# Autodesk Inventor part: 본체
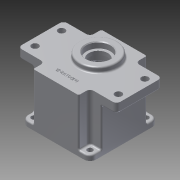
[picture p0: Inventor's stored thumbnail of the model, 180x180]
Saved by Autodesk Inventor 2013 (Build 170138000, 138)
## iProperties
Created: 2015-07
Part Number: 본체
Material: 알루미늄 6061
Document SubType Name: Modeling
Designer: user
Density: 2.71 g/cm^3
Mass: 705.358 g
Surface Area: 672.962 cm^2
Volume: 260.28 cm^3
Author: user
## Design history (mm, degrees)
sketch "스케치1"
  geometry: L1 (-45, 45)-(45, 45); L2 (45, 45)-(45, -45); L3 (45, -45)-(-45, -45); L4 (-45, -45)-(-45, 45); 3 further points
  constraints: 8 end point, 2 midpoint, 2 parallel, 1 horizontal, 1 horizontal alignment, 1 perpendicular, 1 vertical alignment
  dimensions: "d0" = 90 distance of L2.end L3.end; "d1" = 90 distance of L1.end L2.end
extrude "돌출1" new body sketch "스케치1" distance "d2" = 7; taper "d3" = 0 deg
sketch "스케치2"
  geometry: L1 (45, 45)-(-45, 45) reference; L2 (-45, 45)-(-45, -45) reference; L3 (45, -45)-(45, 45) reference; L4 (-30, 45)-(30, 45); L5 (45, 30)-(45, -30); L6 (30, 45)-(30, 30); L7 (30, 30)-(45, 30); L8 (0, 0)-(-18.356, 0); L9 (30, -45)-(30, -30); L10 (30, -30)-(45, -30); L11 (30, -45)-(-30, -45); L12 (-30, -45)-(-30, -30); L13 (-30, -30)-(-45, -30); L14 (-45, -30)-(-45, 30); L15 (-45, 30)-(-30, 30); L16 (-30, 30)-(-30, 45); 2 further points
  constraints: 26 end point, 6 perpendicular, 4 midpoint, 4 parallel, 2 point on line, 2 symmetric about line
  dimensions: "d4" = 60 distance of L4.start L4.end; "d5" = 60 distance of L5.start L5.end; "d6" = 60 distance of L9.start L11.end; "d7" = 60 distance of L13.end L14.end; "d8" = 15 distance between parallel lines of L15 L1; "d9" = 63.35565 distance from line of L8.end L3
extrude "돌출2" join sketch "스케치2" distance "d10" = 51; taper "d11" = 0 deg
sketch "스케치3"
  geometry: L1 (30, 45)-(-30, 45) reference; L2 (-30, 45)-(-30, 30) reference; L3 (-30, -30)-(-30, -45) reference; L4 (-30, -45)-(30, -45) reference; L5 (30, -45)-(30, -30) reference; L6 (45, 30)-(30, 30) reference; L7 (30, 30)-(30, 45) reference; L8 (-30, 45)-(30, 45); L9 (30, 30)-(30, 45); L10 (-65, -30)-(-30, -30); L11 (-30, -30)-(-30, -45); L12 (-30, -45)-(30, -45); L13 (30, -45)-(30, -30); L14 (30, -30)-(65, -30); L15 (-30, 45)-(-30, 30); L16 (-30, 30)-(-65, 30); L17 (30, 30)-(65, 30); L18 (-65, 30)-(-65, -30); L19 (65, -30)-(65, 30); L20 (0, 0)-(-65, 0)
  constraints: 26 end point, 7 collinear, 3 perpendicular, 1 midpoint, 1 parallel
  dimensions: "d12" = 130 distance of L16.end L17.end; "d13" = 60 distance of L16.end L10.start; "d14" = 35 distance between parallel lines of L2 L18
extrude "돌출3" join sketch "스케치3" distance "d15" = 12; taper "d16" = 0 deg
fillet "모깎기1" dims "d17" = 8
fillet "모깎기2" dims "d18" = 5
sketch "스케치4"
  geometry: C1 r 40 at (0, 0); 1 further point
  constraints: 1 centre point, 1 coincident
  dimensions: "d24" = 80 diameter of C1
extrude "돌출4" cut sketch "스케치4" distance "d25" = 9; taper "d26" = 0 deg
sketch "스케치5"
  geometry: C1 r 40 at (0, 0) reference; C2 r 39 at (0, 0)
  constraints: 1 centre point, 1 coincident
  dimensions: "d27" = 78 diameter of C2
extrude "돌출5" cut sketch "스케치5" distance "d28" = 52; taper "d29" = 0 deg
sketch "스케치6"
  geometry: L1 (0, 0)-(0, 11); L2 (0, 0)-(0, -20); C1 r 39 at (0, 0) reference; C2 r 20.5 at (0, 11); C3 r 14 at (0, -20)
  constraints: 4 end point, 2 centre point, 2 coincident, 1 collinear, 1 vertical
  dimensions: "d30" = 11 distance of L1.start L1.end; "d31" = 41 diameter of C2; "d32" = 20 distance of L1.start L2.end; "d33" = 28 diameter of C3
extrude "돌출6" join sketch "스케치6" distance "d34" = 7; taper "d35" = 0 deg
sketch "스케치7"
  geometry: L1 (30, 30)-(30, 45) reference; L2 (0, 0)-(0, 11); C1 r 25 at (0, 11); 2 further points
  constraints: 2 end point, 1 centre point, 1 coincident, 1 parallel
  dimensions: "d36" = 11 distance of L2.start L2.end; "d37" = 50 diameter of C1
extrude "돌출7" join sketch "스케치7" distance "d38" = 7; taper "d39" = 0 deg
sketch "스케치8"
  geometry: C1 r 25 at (0, 0) reference; C2 r 16 at (0, 0); 1 further point
  constraints: 1 centre point, 1 coincident
  dimensions: "d40" = 32 diameter of C2
extrude "돌출8" cut sketch "스케치8" distance "d41" = 8; taper "d42" = 0 deg
sketch "스케치9"
  geometry: C1 r 17.5 at (0, 11); A1 r 20.5 centre (0, 11) between (7.402, -8.117) and (-7.402, -8.117) reference; 1 further point
  constraints: 1 centre point, 1 coincident
  dimensions: "d43" = 35 diameter of C1
extrude "돌출9" cut sketch "스케치9" distance "d44" = 10; taper "d45" = 0 deg
sketch "스케치10"
  geometry: C1 r 17.5 at (0, 0) reference; C2 r 12.5 at (0, 0); 1 further point
  constraints: 1 centre point, 1 coincident
  dimensions: "d46" = 25 diameter of C2
extrude "돌출10" cut sketch "스케치10" distance "d47" = 5; taper "d48" = 0 deg
sketch "스케치11"
  geometry: C1 r 11 at (0, -20); A1 r 14 centre (0, -20) between (-7.402, -8.117) and (7.402, -8.117) reference; 1 further point
  constraints: 1 centre point, 1 coincident
  dimensions: "d49" = 22 diameter of C1
extrude "돌출11" cut sketch "스케치11" distance "d50" = 7; taper "d51" = 0 deg
sketch "스케치12"
  geometry: C1 r 11 at (0, 0) reference; C2 r 9.5 at (0, 0); 1 further point
  constraints: 1 centre point, 1 coincident
  dimensions: "d52" = 19 diameter of C2
extrude "돌출12" cut sketch "스케치12" distance "d53" = 1; taper "d54" = 0 deg
fillet "모깎기8" dims "d55" = 0.3
fillet "모깎기9" dims "d56" = 2
fillet "모깎기10" dims "d57" = 0.3
chamfer "모따기1" distance "d58" = 1; stored, may be unused: second distance "d59" = 2, angle "d60" = 45 deg
fillet "모깎기11" dims "d61" = 2
fillet "모깎기12" dims "d62" = 3
fillet "모깎기13" dims "d63" = 2
sketch "스케치13"
  geometry: L1 (0, 0)-(24.749, 24.749); L2 (0, 0)-(35, 0); C1 r 40 at (0, 0) reference; A1 r 39 centre (0, 0) between (21.134, 32.777) and (32.777, 21.134) reference; A2 r 4 centre (24.749, 24.749) between (21.809, 27.462) and (27.462, 21.809); A3 r 3.5 centre (29.836, 19.238) between (32.777, 21.134) and (27.462, 21.809); A4 r 3.5 centre (19.238, 29.836) between (21.809, 27.462) and (21.134, 32.777); A5 r 39 centre (0, 0) between (32.777, 21.134) and (21.134, 32.777); A6 r 4 centre (-24.749, 24.749) between (-27.462, 21.809) and (-21.809, 27.462); A7 r 3.5 centre (-19.238, 29.836) between (-21.134, 32.777) and (-21.809, 27.462); A8 r 3.5 centre (-29.836, 19.238) between (-27.462, 21.809) and (-32.777, 21.134); A9 r 39 centre (0, 0) between (-21.134, 32.777) and (-32.777, 21.134); A10 r 4 centre (-24.749, -24.749) between (-21.809, -27.462) and (-27.462, -21.809); A11 r 3.5 centre (-29.836, -19.238) between (-32.777, -21.134) and (-27.462, -21.809); A12 r 3.5 centre (-19.238, -29.836) between (-21.809, -27.462) and (-21.134, -32.777); A13 r 39 centre (0, 0) between (-32.777, -21.134) and (-21.134, -32.777); A14 r 4 centre (24.749, -24.749) between (27.462, -21.809) and (21.809, -27.462); A15 r 3.5 centre (19.238, -29.836) between (21.134, -32.777) and (21.809, -27.462); A16 r 3.5 centre (29.836, -19.238) between (27.462, -21.809) and (32.777, -21.134); A17 r 39 centre (0, 0) between (21.134, -32.777) and (32.777, -21.134)
  constraints: 34 point on circle, 16 centre point, 4 end point, 4 tangent, 3 coincident, 1 concentric, 1 equal length, 1 horizontal, 49 other
  dimensions: "d66" = 45 deg angle of L2 L1; "d67" = 8 diameter of A2; "d68" = 7 diameter of A3; "d69" = 7 diameter of A4; "d70" = 14.988 distance of A4.centre A3.centre; "d73" = 360 deg dimension on A1.centre A2.centre (derived)
extrude "돌출13" join sketch "스케치13" stored distance "d75" = 1; taper "d76" = 0 deg
fillet "모깎기15" dims "d77" = 2
sketch "스케치14"
  geometry: A1 r 4 centre (24.749, -24.749) between (27.462, -21.809) and (21.809, -27.462) reference; A2 r 4 centre (-24.749, -24.749) between (-21.809, -27.462) and (-27.462, -21.809) reference; A3 r 4 centre (-24.749, 24.749) between (-27.462, 21.809) and (-21.809, 27.462) reference; A4 r 4 centre (24.749, 24.749) between (21.809, 27.462) and (27.462, 21.809) reference; 4 further points
  constraints: 4 coincident
hole "구멍1" sketch "스케치14" at (-24.749, 24.749), (-24.749, -24.749), (24.749, -24.749), (24.749, 24.749) diameter "d78" = 3.459; stored, may be unused: countersink angle "d82" = 90 deg, drill point angle "d84" = 118 deg; dims "d79" = 12, "d80" = 4, "d81" = 2, "d83" = 15
sketch "스케치15"
  geometry: L1 (-45, -30)-(-45, 30) reference; L2 (30, -45)-(-30, -45) reference; L3 (30, 30)-(45, 30) reference; L4 (45, 37)-(45, 30) reference; L5 (30, 45)-(37, 45) reference; L6 (30, 45)-(30, 30) reference; L7 (45, 30)-(45, -30) reference; L8 (45, -30)-(45, -37) reference; L9 (37, -45)-(30, -45) reference; L10 (30, -30)-(30, -45) reference; L11 (45, -30)-(30, -30) reference; L12 (-30, 45)-(30, 45) reference; L13 (-30, 30)-(-30, 45) reference; L14 (-45, 30)-(-30, 30) reference; L15 (-37, 45)-(-30, 45) reference; L16 (-45, 30)-(-45, 37) reference; L17 (-30, -45)-(-30, -30) reference; L18 (-30, -30)-(-45, -30) reference; L19 (-30, -45)-(-37, -45) reference; L20 (-45, -37)-(-45, -30) reference; C1 r 40 at (0, 0) reference; C2 r 3.5 at (-37, 37); C3 r 3.5 at (37, 37); C4 r 3.5 at (37, -37); C5 r 3.5 at (-37, -37); A1 r 8 centre (37, 37) between (45, 37) and (37, 45) reference; A2 r 8 centre (37, -37) between (37, -45) and (45, -37) reference; A3 r 8 centre (-37, 37) between (-37, 45) and (-45, 37) reference; A4 r 8 centre (-37, -37) between (-45, -37) and (-37, -45) reference; 1 further point
  constraints: 4 centre point
  dimensions: "d85" = 7 diameter of C2; "d86" = 7 diameter of C3; "d87" = 7 diameter of C4; "d88" = 7 diameter of C5
extrude "돌출14" cut sketch "스케치15" distance "d89" = 7; taper "d90" = 0 deg
sketch "스케치16"
  geometry: L1 (-55, 17.5)-(55, 17.5); L2 (55, 17.5)-(55, -17.5); L3 (55, -17.5)-(-55, -17.5); L4 (-55, -17.5)-(-55, 17.5); C1 r 4.5 at (-55, 17.5); C2 r 4.5 at (-55, -17.5); C3 r 4.5 at (55, -17.5); C4 r 4.5 at (55, 17.5); 3 further points
  constraints: 8 end point, 4 centre point, 4 coincident, 2 midpoint, 2 parallel, 1 horizontal, 1 horizontal alignment, 1 perpendicular, 1 vertical alignment
  dimensions: "d93" = 110 distance of L2.end L3.end; "d94" = 35 distance of L1.end L2.end; "d95" = 9 diameter of C1; "d96" = 9 diameter of C2; "d97" = 9 diameter of C3; "d98" = 9 diameter of C4
extrude "돌출15" cut sketch "스케치16" distance "d99" = 12; taper "d100" = 0 deg
sketch "스케치17"
  geometry: L1 (-30, -45)-(30, -45) reference; L2 (-30, -30)-(-30, -45) reference; L3 (0, -45)-(0, -30); 6 further points
  constraints: 2 end point, 1 coincident, 1 midpoint, 1 parallel, 1 other
  dimensions: "d101" = 15 distance of L3.start L3.end
feature "엠보싱1" sketch "스케치17" dims "d4" = 60, "d5" = 60, "d6" = 60, "d7" = 60, "d8" = 15, "d9" = 63.35565, "d102" = 0.5, "d103" = 0
fillet "모깎기18" dims "d104" = 2
fillet "모깎기19" dims "d105" = 2
fillet "모깎기20" dims "d106" = 5
fillet "모깎기21" dims "d107" = 2
node "솔리드1"
node "절단 모서리 투영1"
